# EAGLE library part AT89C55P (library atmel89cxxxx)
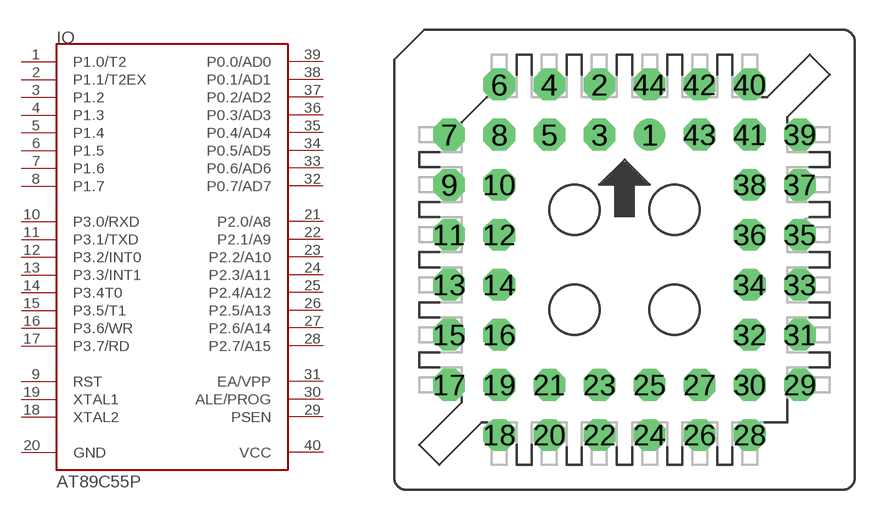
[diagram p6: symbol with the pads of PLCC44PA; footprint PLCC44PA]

Designator prefix IO

## AT89C55P  [PLCC44PA]
1  P1.0/T2
2  P1.1/T2EX
3  P1.2
4  P1.3
5  P1.4
6  P1.5
7  P1.6
8  P1.7
9  RST
10  P3.0/RXD
11  P3.1/TXD
12  P3.2/INT0
13  P3.3/INT1
14  P3.4T0
15  P3.5/T1
16  P3.6/WR
17  P3.7/RD
18  XTAL2
19  XTAL1
20  GND  pwr
21  P2.0/A8
22  P2.1/A9
23  P2.2/A10
24  P2.3/A11
25  P2.4/A12
26  P2.5/A13
27  P2.6/A14
28  P2.7/A15
29  PSEN
30  ALE/PROG
31  EA/VPP
32  P0.7/AD7
33  P0.6/AD6
34  P0.5/AD5
35  P0.4/AD4
36  P0.3/AD3
37  P0.2/AD2
38  P0.1/AD1
39  P0.0/AD0
40  VCC  pwr

## Footprint PLCC44PA (pad centres in mm)
drill 0.813 pad 1.6 round: 1 1.27,6.35
drill 0.813 pad 1.6 octagon: 2 -1.27,8.89; 3 -1.27,6.35; 4 -3.81,8.89; 5 -3.81,6.35; 6 -6.35,8.89; 7 -8.89,6.35; 8 -6.35,6.35; 9 -8.89,3.81; 10 -6.35,3.81; 11 -8.89,1.27; 12 -6.35,1.27; 13 -8.89,-1.27; 14 -6.35,-1.27; 15 -8.89,-3.81; 16 -6.35,-3.81; 17 -8.89,-6.35; 18 -6.35,-8.89; 19 -6.35,-6.35; 20 -3.81,-8.89; 21 -3.81,-6.35; 22 -1.27,-8.89; 23 -1.27,-6.35; 24 1.27,-8.89; 25 1.27,-6.35; 26 3.81,-8.89; 27 3.81,-6.35; 28 6.35,-8.89; 29 8.89,-6.35; 30 6.35,-6.35; 31 8.89,-3.81; 32 6.35,-3.81; 33 8.89,-1.27; 34 6.35,-1.27; 35 8.89,1.27; 36 6.35,1.27; 37 8.89,3.81; 38 6.35,3.81; 39 8.89,6.35; 40 6.35,8.89; 41 6.35,6.35; 42 3.81,8.89; 43 3.81,6.35; 44 1.27,8.89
